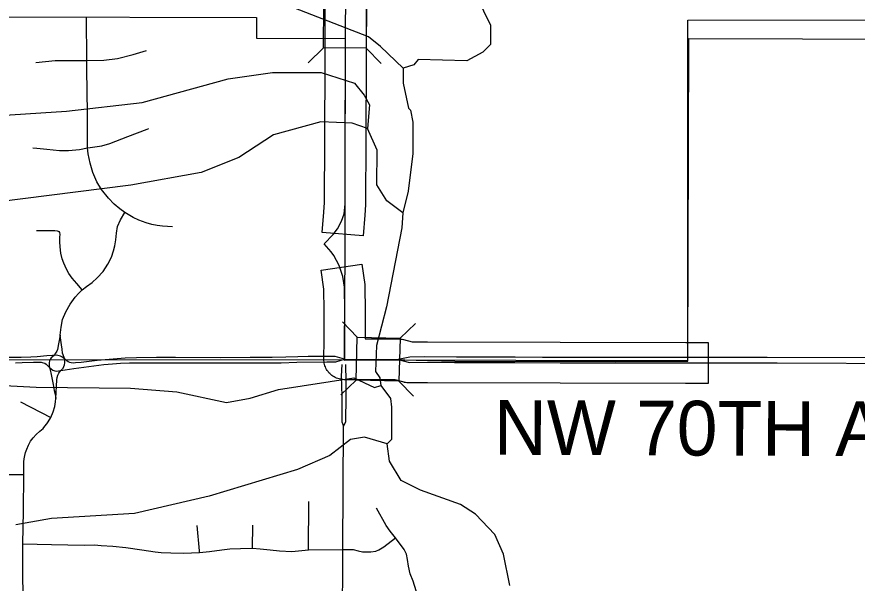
# Model space of a CAD drawing. Extents: x -1403959 to 81668, y -1400582 to 11018.
# Drawn here: x 6561.9 to 6680.8, y 8886.6 to 8966.7 of the extents above; entities that cross this region are included whole.
import ezdxf

# ---------------------------------------------------------------- set-up
doc = ezdxf.new("R2010")
doc.units = 0
for name, color, linetype in [('tdCiCoBndryTxt', 7, 'Continuous'), ('tdCiRRCL', 7, 'Continuous'), ('tdCiRROwnerTxt', 7, 'Continuous'), ('tdCiSecText', 7, 'Continuous'), ('tdCiSectLine', 7, 'Continuous'), ('tdCiSectNmbr', 7, 'Continuous'), ('tdCiSectTwpRng', 7, 'Continuous'), ('tdCiUABTitleFrame', 7, 'Continuous'), ('tdCoClipBndry', 7, 'Continuous'), ('tdCoSectNmbr', 7, 'Continuous'), ('tdCoSurfBitum', 7, 'Continuous')]:
    doc.layers.add(name, color=color, linetype=linetype)

msp = doc.modelspace()

# ---------------------------------------------------------------- linework, layer by layer
at = {"layer": 'tdCiCoBndryTxt'}
for points in [[(6608.4, 8963.67), (6608.42, 8970.42), (6608.52, 8982.49), (6608.52, 8994.81), (6608.6, 9008.75), (6608.63, 9014.88)], [(6608.33, 8940.34), (6608.34, 8949.28), (6608.39, 8960.65), (6608.4, 8963.67)], [(6608.4, 8963.67), (6608.4, 8963.67)]]:
    msp.add_lwpolyline(points, dxfattribs=at)
at = {"layer": 'tdCiRRCL'}
msp.add_lwpolyline([(6560.03, 8990.81), (6559.88, 8966.7), (6595.81, 8966.63), (6595.8, 8963.69), (6608.35, 8963.67), (6608.29, 8942.27), (6608.22, 8918.15), (6610.92, 8918.24), (6613.03, 8918.3), (6615.15, 8918.25), (6620.05, 8918.13), (6623.85, 8918.03), (6646.63, 8917.98), (6656.81, 8918.03), (6656.83, 8966.23), (6697.02, 8966.29), (6704.54, 8966.31), (6704.58, 8972.16)], dxfattribs=at)
at = {"layer": 'tdCiRROwnerTxt'}
for points in [[(6608.28, 8939.76), (6608.33, 8940.34)], [(6608.21, 8938.87), (6608.28, 8939.74), (6608.28, 8939.76)], [(6608.22, 8918.31), (6608.26, 8920.94), (6608.29, 8925.17), (6608.24, 8928.45), (6608.24, 8928.46)], [(6608.22, 8918.31), (6615.82, 8918.27)], [(6615.82, 8918.27), (6617.45, 8917.83)], [(6617.45, 8917.83), (6619.97, 8917.86), (6623.8, 8917.85)], [(6623.8, 8917.85), (6624.12, 8917.85)], [(6624.12, 8917.85), (6628.31, 8917.84)], [(6628.31, 8917.84), (6632.35, 8917.82)], [(6632.35, 8917.82), (6638.75, 8917.8), (6656.52, 8917.78), (6656.8, 8917.78)]]:
    msp.add_lwpolyline(points, dxfattribs=at)
at = {"layer": 'tdCiSecText'}
for points in [[(6613.48, 8970.42), (6611.37, 8968.35), (6611.33, 8962.3)], [(6603.12, 8960.22), (6605.28, 8962.34), (6605.32, 8968.39)], [(6613.45, 8960.14), (6611.33, 8962.3), (6605.28, 8962.34)], [(6607.96, 8923.59), (6610.05, 8921.4), (6616.1, 8921.25)], [(6618.29, 8923.34), (6616.1, 8921.25), (6615.95, 8915.21)], [(6607.72, 8913.26), (6609.91, 8915.35), (6610.05, 8921.4)], [(6618, 8913.06), (6615.95, 8915.21), (6609.91, 8915.35)]]:
    msp.add_lwpolyline(points, dxfattribs=at)
at = {"layer": 'tdCiSectLine'}
for points in [[(6610.88, 8935.75), (6605.09, 8936.2), (6605.32, 8939.1), (6605.43, 8940.45), (6605.44, 8949.29), (6605.44, 8949.29), (6605.49, 8960.66), (6605.52, 8970.43)], [(6611.33, 8970.41), (6611.29, 8960.64), (6611.29, 8960.64), (6611.25, 8949.27), (6611.23, 8940.33), (6611.22, 8940.15), (6611.22, 8940.11), (6611.11, 8938.65), (6610.88, 8935.75)], [(6656.52, 8914.88), (6656.51, 8914.88), (6638.75, 8914.9), (6638.74, 8914.9), (6619.98, 8914.96), (6617.49, 8914.93), (6617.45, 8914.93), (6617.26, 8914.93), (6617.07, 8914.95), (6616.88, 8914.98), (6616.7, 8915.02), (6616.69, 8915.03), (6615.43, 8915.37), (6608.21, 8915.4), (6608.03, 8915.41), (6607.85, 8915.43), (6607.66, 8915.46), (6607.47, 8915.5), (6607.29, 8915.56), (6607.11, 8915.63), (6606.94, 8915.7), (6606.77, 8915.79), (6606.61, 8915.89), (6606.46, 8916), (6606.31, 8916.12), (6606.17, 8916.25), (6606.04, 8916.39), (6605.92, 8916.54), (6605.81, 8916.69), (6605.71, 8916.86), (6605.62, 8917.02), (6605.54, 8917.2), (6605.48, 8917.37), (6605.42, 8917.56), (6605.38, 8917.74), (6605.35, 8917.93), (6605.33, 8918.12), (6605.32, 8918.31), (6605.32, 8918.35), (6605.36, 8920.97), (6605.38, 8925.16), (6605.34, 8928.22), (6604.95, 8930.91), (6610.69, 8931.75), (6611.11, 8928.87), (6611.11, 8928.87), (6611.11, 8928.83), (6611.13, 8928.64), (6611.14, 8928.49), (6611.19, 8925.21), (6611.19, 8925.17), (6611.19, 8925.15), (6611.17, 8921.19), (6615.84, 8921.17), (6616.01, 8921.16), (6616.2, 8921.15), (6616.39, 8921.11), (6616.57, 8921.07), (6616.58, 8921.07), (6617.81, 8920.73), (6619.92, 8920.77), (6619.97, 8920.77), (6619.98, 8920.77), (6638.76, 8920.7), (6656.52, 8920.68), (6656.79, 8920.68), (6659.69, 8920.68), (6659.7, 8914.88), (6656.8, 8914.88), (6656.52, 8914.88), (6656.52, 8914.88)]]:
    msp.add_lwpolyline(points, dxfattribs=at)
at = {"layer": 'tdCiSectNmbr'}
for points in [[(6561.67, 8917.78), (6562.61, 8917.82), (6564.25, 8917.87), (6564.91, 8917.89), (6565.17, 8917.89), (6565.33, 8917.88), (6565.48, 8917.85), (6565.65, 8917.8), (6565.84, 8917.72), (6566.02, 8917.61), (6566.14, 8917.51), (6566.33, 8917.33), (6566.52, 8917.11), (6566.79, 8916.87), (6566.99, 8916.76), (6567.27, 8916.65), (6567.53, 8916.61), (6567.77, 8916.63), (6568.08, 8916.68), (6569.95, 8916.96), (6573.49, 8917.45), (6574.21, 8917.55), (6575.41, 8917.66), (6576.56, 8917.72), (6577.8, 8917.76), (6579.09, 8917.76), (6583.95, 8917.76), (6590.54, 8917.76), (6596.19, 8917.79), (6599.28, 8917.79), (6601.51, 8917.86), (6605.73, 8917.92), (6607, 8917.91)], [(6607, 8917.91), (6608.22, 8918.31)], [(6656.8, 8917.78), (6669.48, 8917.8), (6689.03, 8917.67), (6706.43, 8917.69), (6724.75, 8917.76), (6729.86, 8917.73), (6735.68, 8917.8), (6738.81, 8917.71), (6743.58, 8917.47), (6747.1, 8917.39), (6747.82, 8917.38), (6752.66, 8917.36), (6756.61, 8917.39), (6759.7, 8917.29), (6760.37, 8917.28), (6767.56, 8917.39), (6770.6, 8917.39), (6772.95, 8917.39), (6776.68, 8917.49), (6783.85, 8917.54), (6792.45, 8917.49), (6795.01, 8917.52), (6796.71, 8917.53)], [(6607.87, 8917.55), (6607.76, 8915.88), (6607.85, 8913.05)], [(6608.46, 8913.06), (6608.47, 8915.14), (6608.43, 8917.54)], [(6607.85, 8913.05), (6607.85, 8913), (6607.87, 8909.44), (6608.1, 8908.81)], [(6608.1, 8908.81), (6608.45, 8909.42), (6608.46, 8913.06)], [(6607.59, 8825.91), (6607.81, 8854.05), (6607.85, 8861.28), (6607.92, 8871.72), (6607.98, 8880.45), (6608.03, 8891.36), (6608.1, 8908.81)]]:
    msp.add_lwpolyline(points, dxfattribs=at)
at = {"layer": 'tdCiSectTwpRng'}
for points in [[(6583.89, 8937.04), (6582.49, 8937.11), (6581.74, 8937.21), (6580.98, 8937.35), (6580.16, 8937.56), (6579.16, 8937.94), (6578.35, 8938.35), (6577.17, 8939.03), (6576.45, 8939.58), (6575.64, 8940.24), (6574.87, 8941.06), (6573.88, 8942.28), (6573.22, 8943.4), (6572.61, 8944.72), (6572.23, 8946), (6571.99, 8947.35), (6571.88, 8948.17), (6571.86, 8950.24), (6571.88, 8954.3), (6571.85, 8954.95), (6571.8, 8960.53), (6571.74, 8966.68)], [(6564.58, 8960.27), (6567.3, 8960.56), (6571.8, 8960.53), (6574.2, 8960.59), (6576.1, 8960.84), (6578.35, 8961.38), (6580.23, 8961.95)], [(6571.9, 8948.17), (6573.91, 8948.48), (6575.02, 8948.79), (6577.57, 8949.77), (6580.31, 8950.84)], [(6580.31, 8950.84), (6580.57, 8950.94)], [(6564.12, 8948.19), (6564.72, 8948.13)], [(6564.72, 8948.13), (6566.11, 8947.99), (6567.92, 8947.83), (6569.17, 8947.83), (6570.74, 8947.96), (6571.88, 8948.17), (6571.9, 8948.17)], [(6567.99, 8921.68), (6568.13, 8922.82), (6568.35, 8923.9), (6568.79, 8924.98), (6569.41, 8926.08), (6570.11, 8927.05), (6570.63, 8927.63), (6571.1, 8928.11), (6571.72, 8928.57), (6572.53, 8929.12), (6573.26, 8929.82), (6574.09, 8930.72), (6574.75, 8931.72), (6575.27, 8932.75), (6575.56, 8933.62), (6575.74, 8934.33), (6575.87, 8935.17), (6575.97, 8936.1), (6576.13, 8937.05), (6576.56, 8938.03), (6577.17, 8939.03)], [(6608.24, 8928.46), (6608.01, 8929.99), (6607.47, 8931.56), (6606.75, 8932.95), (6606.35, 8933.47), (6605.35, 8934.59), (6606.62, 8935.94), (6607.25, 8936.74), (6607.84, 8937.8), (6608.21, 8938.87)], [(6564.65, 8936.48), (6565.84, 8936.49), (6567.25, 8936.48), (6567.59, 8936.47), (6567.89, 8936.34)], [(6571.1, 8928.11), (6570.35, 8928.98), (6569.7, 8929.77), (6569.22, 8930.43), (6568.9, 8931.02), (6568.51, 8931.9), (6568.29, 8932.51), (6568.12, 8933.3), (6568.01, 8934.17), (6567.97, 8934.88), (6567.98, 8935.54), (6567.99, 8935.91), (6567.94, 8936.2), (6567.89, 8936.34)], [(6567.99, 8921.68), (6567.8, 8920.72), (6567.73, 8920.21), (6567.68, 8919.89), (6567.61, 8919.66), (6567.52, 8919.42), (6567.36, 8919.13), (6567.15, 8918.84)], [(6567.41, 8912.72), (6567.56, 8915.39), (6567.59, 8915.7), (6567.69, 8916.02), (6567.84, 8916.32), (6567.91, 8916.44), (6568.08, 8916.68), (6568.26, 8916.83), (6568.44, 8917.05), (6568.54, 8917.27), (6568.62, 8917.49), (6568.66, 8917.8), (6568.68, 8918.12), (6568.66, 8918.32), (6568.36, 8919.15), (6568.27, 8919.7), (6568.18, 8920.33), (6568.09, 8921), (6567.99, 8921.68)], [(6567.15, 8918.84), (6566.91, 8918.82), (6566.14, 8918.75), (6564.74, 8918.64), (6563.85, 8918.58), (6562.47, 8918.54), (6548.87, 8918.54), (6540.77, 8918.55), (6534.95, 8918.58), (6525.52, 8918.54), (6524.65, 8918.6)], [(6567.15, 8918.84), (6566.92, 8918.65), (6566.73, 8918.47), (6566.58, 8918.26), (6566.51, 8918.08), (6566.45, 8917.78), (6566.45, 8917.42), (6566.52, 8917.11)], [(6568.66, 8918.32), (6568.45, 8918.48), (6568.26, 8918.63), (6568.04, 8918.73), (6567.88, 8918.79), (6567.69, 8918.84), (6567.48, 8918.85), (6567.15, 8918.84)], [(6606.92, 8918.67), (6604.85, 8918.67), (6603.1, 8918.67), (6601.65, 8918.65), (6599.95, 8918.59), (6597.99, 8918.53), (6594.89, 8918.53), (6590.7, 8918.5), (6584.35, 8918.53), (6581.65, 8918.53), (6578.81, 8918.5), (6577.2, 8918.42), (6574.95, 8918.26), (6573.26, 8918.11), (6570.97, 8917.83), (6570.16, 8917.76), (6569.84, 8917.74), (6569.58, 8917.78), (6569.36, 8917.83), (6569.15, 8917.93), (6568.94, 8918.06), (6568.66, 8918.32)], [(6608.22, 8918.31), (6606.92, 8918.67)], [(6656.81, 8918.53), (6656.81, 8918.53)], [(6796.98, 8918.27), (6790.25, 8918.28), (6784.96, 8918.28), (6767.8, 8918.1), (6760.1, 8918.13), (6751.1, 8918.12), (6747.58, 8918.14), (6745.32, 8918.15), (6742.41, 8918.25), (6739.74, 8918.41), (6736.89, 8918.49), (6733.16, 8918.47), (6729.85, 8918.46), (6720.78, 8918.43), (6703.6, 8918.41), (6685.9, 8918.47), (6668.07, 8918.52), (6656.81, 8918.53)], [(6566.52, 8917.11), (6566.69, 8916.36), (6567.01, 8914.71), (6567.17, 8913.85), (6567.28, 8913.33), (6567.41, 8912.72)], [(6562.41, 8912.27), (6566.69, 8910.06)], [(6562.81, 8896.81), (6562.85, 8902), (6562.85, 8903.19), (6562.85, 8903.76), (6562.92, 8904.2), (6563.01, 8904.68), (6563.12, 8905.12), (6563.27, 8905.59), (6563.52, 8906.14), (6563.81, 8906.69), (6564.18, 8907.19), (6564.6, 8907.65), (6565.15, 8908.14), (6565.59, 8908.51), (6565.86, 8908.82), (6566.12, 8909.16), (6566.32, 8909.45), (6566.69, 8910.06), (6567.03, 8910.83), (6567.25, 8911.6), (6567.36, 8912.27), (6567.41, 8912.72)], [(6559.61, 8901.98), (6562.85, 8902)], [(6603.16, 8891.31), (6603.18, 8898.17)], [(6562.73, 8887.7), (6562.74, 8892.16), (6562.81, 8896.81)], [(6619.65, 8882.35), (6619.03, 8883.86), (6618.4, 8885.54), (6617.94, 8886.88), (6617.54, 8887.92), (6617.28, 8889.03), (6617.14, 8889.95), (6617.02, 8890.71), (6616.7, 8891.4), (6615.45, 8893.03), (6614.71, 8893.99), (6614.16, 8894.77), (6612.78, 8897.22)], [(6587.71, 8891.21), (6587.41, 8894.77)], [(6595.22, 8891.56), (6595.29, 8894.82)], [(6608.03, 8891.36), (6609.47, 8891.36), (6610.16, 8891.19), (6610.81, 8891.06), (6611.39, 8891.04), (6611.96, 8891.04), (6612.67, 8891.15), (6613.11, 8891.34), (6613.8, 8891.76), (6615.45, 8893.03)], [(6562.74, 8892.16), (6566.76, 8892.09), (6571.42, 8892), (6572.88, 8892.02), (6573.82, 8891.95), (6575.47, 8891.83), (6577.29, 8891.66), (6579.57, 8891.32), (6581.47, 8891.04), (6582.31, 8890.97), (6583.69, 8890.89), (6585.46, 8890.87), (6587.74, 8890.97), (6589.13, 8891.09), (6590.89, 8891.34), (6592.01, 8891.48), (6593.53, 8891.54), (6595.22, 8891.56), (6596.33, 8891.49), (6597.71, 8891.34), (6599.05, 8891.17), (6600.77, 8891.11), (6603.16, 8891.31), (6608.03, 8891.36), (6608.03, 8891.36)], [(6587.74, 8890.97), (6587.71, 8891.21)], [(6568.76, 8860), (6568.13, 8860.94), (6567.66, 8861.7), (6567.2, 8862.73), (6566.45, 8864.76), (6565.02, 8868.94), (6564.63, 8870.48), (6564.33, 8871.8), (6563.94, 8874), (6563.4, 8878.96), (6563.03, 8882.12), (6562.92, 8883.36), (6562.87, 8884.24), (6562.79, 8885.11), (6562.73, 8887.68), (6562.73, 8887.7)]]:
    msp.add_lwpolyline(points, dxfattribs=at)
at = {"layer": 'tdCiUABTitleFrame'}
for points in [[(6617.5, 8918.57), (6615.82, 8918.27)], [(6624.11, 8918.6), (6619.6, 8918.62), (6617.5, 8918.57)], [(6628.73, 8918.58), (6624.11, 8918.6)], [(6632.3, 8918.56), (6628.73, 8918.58)], [(6632.41, 8918.56), (6632.3, 8918.56)], [(6656.81, 8918.53), (6651.31, 8918.54), (6636.28, 8918.54), (6632.41, 8918.56)]]:
    msp.add_lwpolyline(points, dxfattribs=at)
at = {"layer": 'tdCoClipBndry'}
msp.add_lwpolyline([(6705.37, 9009.39), (6705.3, 8963.48), (6656.93, 8963.62), (6656.78, 8918.07), (6608.19, 8918.16), (6511.17, 8918.25), (6510.5, 8815.52), (6509.95, 8718.68)], dxfattribs=at)
at = {"layer": 'tdCoSurfBitum'}
for points in [[(6626.94, 8969.66), (6628.92, 8965.54), (6628.91, 8962.79), (6627.84, 8961.72), (6625.55, 8960.51), (6618.68, 8960.68), (6618.06, 8959.91), (6616.54, 8959.46), (6613.34, 8962.52), (6611.66, 8963.9), (6597.93, 8969.27)], [(6616.54, 8959.46), (6616.53, 8957.32), (6617.29, 8953.81), (6617.59, 8953.5), (6617.89, 8951.82), (6617.89, 8947.4), (6617.26, 8942.05), (6616.49, 8939), (6614.21, 8940.69), (6612.84, 8942.98), (6612.85, 8947.86), (6611.48, 8950.92)], [(6559.44, 8952.76), (6568.9, 8953.37), (6579.59, 8954.59), (6591.8, 8957.95), (6598.06, 8958.86), (6604.93, 8958.86), (6609.66, 8957.33), (6611.03, 8955.66), (6611.79, 8954.28), (6611.48, 8950.92), (6609.34, 8951.69), (6604.91, 8951.85), (6598.19, 8950.04), (6593.3, 8946.84), (6587.95, 8944.71), (6578.02, 8942.91), (6558.93, 8940.51)], [(6616.49, 8939), (6616.34, 8936.86), (6614.18, 8925.72), (6612.79, 8920.23), (6612.63, 8916.57), (6613.24, 8915.65), (6613.39, 8914.58)], [(6557.4, 8914.71), (6564.59, 8914.34), (6577.94, 8914.19), (6584.54, 8913.67), (6591.55, 8912.18), (6594.91, 8912.79), (6598.88, 8914), (6609.57, 8915.66), (6612.47, 8914.28), (6613.39, 8914.58), (6614.76, 8912.75), (6614.91, 8911.52), (6614.9, 8906.94), (6614.29, 8906.34), (6611.08, 8907.26), (6609.1, 8906.96), (6606.19, 8904.67), (6601.61, 8902.7), (6589.08, 8898.91), (6578.54, 8896.49), (6566.78, 8895.76), (6561.73, 8894.85)], [(6631.66, 8886.3), (6630.75, 8890.73), (6629.53, 8893.48), (6626.79, 8896.38), (6624.66, 8897.76), (6619.01, 8899.76), (6616.26, 8901.14), (6614.59, 8903.89), (6614.29, 8906.34)]]:
    msp.add_lwpolyline(points, dxfattribs=at)

# ---------------------------------------------------------------- texts
at = {"layer": 'tdCoSectNmbr'}
msp.add_text('NW 70TH AVE', height=7.7382, rotation=359.7848, dxfattribs=at).set_placement((6629.38, 8904.78))

doc.saveas('drawing.dxf')
